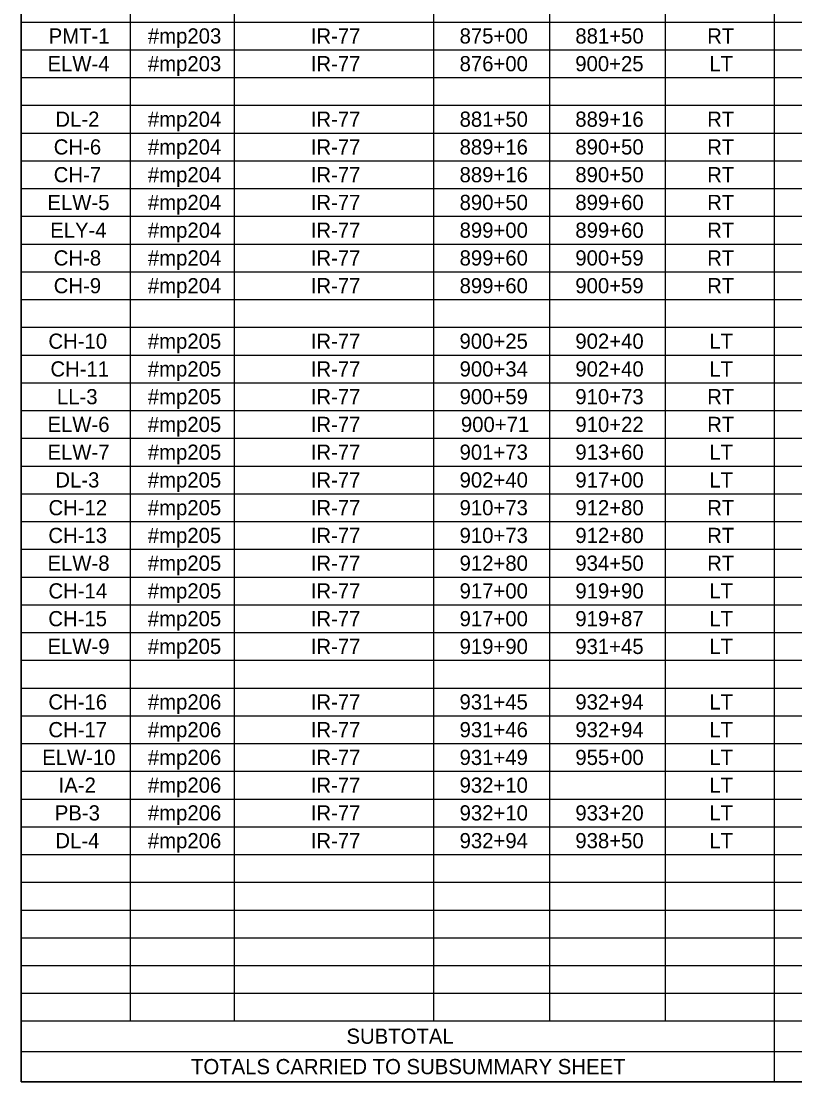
# Model space of a CAD drawing. Extents: x 91011267 to 91022583, y 37007614 to 37014266.
# Drawn here: x 91011277 to 91011661, y 37008895 to 37009420 of the extents above; entities that cross this region are included whole.
import ezdxf

# ---------------------------------------------------------------- set-up
doc = ezdxf.new("R2010")
doc.units = 0
doc.layers.add('SC_Scratch2', color=7, linetype='Continuous')
doc.layers.add('SH_Data', color=7, linetype='Continuous')

msp = doc.modelspace()

# ---------------------------------------------------------------- linework, layer by layer
at = {"layer": 'SC_Scratch2'}
msp.add_lwpolyline([(91011277.35, 37009944.63), (91012802.35, 37009944.63), (91012802.35, 37008894.63), (91011277.35, 37008894.63)], close=True, dxfattribs=at)
at = {"layer": 'SH_Data'}
for p, q in [((91011277.35, 37009570.43), (91011277.35, 37009364.35)), ((91011331.39, 37009570.43), (91011331.39, 37009364.35)), ((91011382.8, 37009570.43), (91011382.8, 37009364.35)), ((91011481.65, 37009570.43), (91011481.65, 37009364.35)), ((91011538.99, 37009570.43), (91011538.99, 37009364.35)), ((91011596.32, 37009570.43), (91011596.32, 37009364.35)), ((91011650.36, 37009570.43), (91011650.36, 37009364.35)), ((91011277.35, 37009419.31), (91011596.32, 37009419.31)), ((91011596.32, 37009419.31), (91011650.36, 37009419.31)), ((91011650.36, 37009419.31), (91011950.88, 37009419.31)), ((91011277.35, 37009405.57), (91011596.32, 37009405.57)), ((91011596.32, 37009405.57), (91011650.36, 37009405.57)), ((91011650.36, 37009405.57), (91011950.88, 37009405.57)), ((91011277.35, 37009391.83), (91011596.32, 37009391.83)), ((91011596.32, 37009391.83), (91011650.36, 37009391.83)), ((91011650.36, 37009391.83), (91011950.88, 37009391.83)), ((91011277.35, 37009378.09), (91011596.32, 37009378.09)), ((91011596.32, 37009378.09), (91011650.36, 37009378.09)), ((91011650.36, 37009378.09), (91011950.88, 37009378.09)), ((91011277.35, 37009364.35), (91011596.32, 37009364.35)), ((91011277.35, 37009364.35), (91011277.35, 37009350.61)), ((91011331.39, 37009364.35), (91011331.39, 37009350.61)), ((91011382.8, 37009364.35), (91011382.8, 37009350.61)), ((91011481.65, 37009364.35), (91011481.65, 37009350.61)), ((91011538.99, 37009364.35), (91011538.99, 37009350.61)), ((91011596.32, 37009364.35), (91011650.36, 37009364.35)), ((91011596.32, 37009364.35), (91011596.32, 37009350.61)), ((91011650.36, 37009364.35), (91011950.88, 37009364.35)), ((91011650.36, 37009364.35), (91011650.36, 37009350.61)), ((91011277.35, 37009350.61), (91011596.32, 37009350.61)), ((91011277.35, 37009350.61), (91011277.35, 37009336.88)), ((91011331.39, 37009350.61), (91011331.39, 37009336.88)), ((91011382.8, 37009350.61), (91011382.8, 37009336.88)), ((91011481.65, 37009350.61), (91011481.65, 37009336.88)), ((91011538.99, 37009350.61), (91011538.99, 37009336.88)), ((91011596.32, 37009350.61), (91011650.36, 37009350.61)), ((91011596.32, 37009350.61), (91011596.32, 37009336.88)), ((91011650.36, 37009350.61), (91011950.88, 37009350.61)), ((91011650.36, 37009350.61), (91011650.36, 37009336.88)), ((91011277.35, 37009336.88), (91011596.32, 37009336.88)), ((91011277.35, 37009336.88), (91011277.35, 37009295.66)), ((91011331.39, 37009336.88), (91011331.39, 37009295.66)), ((91011382.8, 37009336.88), (91011382.8, 37009295.66)), ((91011481.65, 37009336.88), (91011481.65, 37009295.66)), ((91011538.99, 37009336.88), (91011538.99, 37009295.66)), ((91011596.32, 37009336.88), (91011650.36, 37009336.88)), ((91011596.32, 37009336.88), (91011596.32, 37009295.66)), ((91011650.36, 37009336.88), (91011950.88, 37009336.88)), ((91011650.36, 37009336.88), (91011650.36, 37009295.66)), ((91011277.35, 37009323.14), (91011596.32, 37009323.14)), ((91011596.32, 37009323.14), (91011650.36, 37009323.14)), ((91011650.36, 37009323.14), (91011950.88, 37009323.14)), ((91011277.35, 37009309.4), (91011596.32, 37009309.4)), ((91011596.32, 37009309.4), (91011650.36, 37009309.4)), ((91011650.36, 37009309.4), (91011950.88, 37009309.4)), ((91011277.35, 37009295.66), (91011596.32, 37009295.66)), ((91011277.35, 37009295.66), (91011277.35, 37009281.92)), ((91011331.39, 37009295.66), (91011331.39, 37009281.92)), ((91011382.8, 37009295.66), (91011382.8, 37009281.92)), ((91011481.65, 37009295.66), (91011481.65, 37009281.92)), ((91011538.99, 37009295.66), (91011538.99, 37009281.92)), ((91011596.32, 37009295.66), (91011650.36, 37009295.66)), ((91011596.32, 37009295.66), (91011596.32, 37009281.92)), ((91011650.36, 37009295.66), (91011950.88, 37009295.66)), ((91011650.36, 37009295.66), (91011650.36, 37009281.92)), ((91011277.35, 37009281.92), (91011596.32, 37009281.92)), ((91011277.35, 37009281.92), (91011277.35, 37009268.18)), ((91011331.39, 37009281.92), (91011331.39, 37009268.18)), ((91011382.8, 37009281.92), (91011382.8, 37009268.18)), ((91011481.65, 37009281.92), (91011481.65, 37009268.18)), ((91011538.99, 37009281.92), (91011538.99, 37009268.18)), ((91011596.32, 37009281.92), (91011650.36, 37009281.92)), ((91011596.32, 37009281.92), (91011596.32, 37009268.18)), ((91011650.36, 37009281.92), (91011950.88, 37009281.92)), ((91011650.36, 37009281.92), (91011650.36, 37009268.18)), ((91011277.35, 37009268.18), (91011596.32, 37009268.18)), ((91011277.35, 37009268.18), (91011277.35, 37009226.97)), ((91011331.39, 37009268.18), (91011331.39, 37009226.97)), ((91011382.8, 37009268.18), (91011382.8, 37009226.97)), ((91011481.65, 37009268.18), (91011481.65, 37009226.97)), ((91011538.99, 37009268.18), (91011538.99, 37009226.97)), ((91011596.32, 37009268.18), (91011650.36, 37009268.18)), ((91011596.32, 37009268.18), (91011596.32, 37009226.97)), ((91011650.36, 37009268.18), (91011950.88, 37009268.18)), ((91011650.36, 37009268.18), (91011650.36, 37009226.97)), ((91011277.35, 37009254.45), (91011596.32, 37009254.45)), ((91011596.32, 37009254.45), (91011650.36, 37009254.45)), ((91011650.36, 37009254.45), (91011950.88, 37009254.45)), ((91011277.35, 37009240.71), (91011596.32, 37009240.71)), ((91011596.32, 37009240.71), (91011650.36, 37009240.71)), ((91011650.36, 37009240.71), (91011950.88, 37009240.71)), ((91011277.35, 37009226.97), (91011596.32, 37009226.97)), ((91011277.35, 37009226.97), (91011277.35, 37009213.23)), ((91011331.39, 37009226.97), (91011331.39, 37009213.23)), ((91011382.8, 37009226.97), (91011382.8, 37009213.23)), ((91011481.65, 37009226.97), (91011481.65, 37009213.23)), ((91011538.99, 37009226.97), (91011538.99, 37009213.23)), ((91011596.32, 37009226.97), (91011650.36, 37009226.97)), ((91011596.32, 37009226.97), (91011596.32, 37009213.23)), ((91011650.36, 37009226.97), (91011950.88, 37009226.97)), ((91011650.36, 37009226.97), (91011650.36, 37009213.23)), ((91011277.35, 37009213.23), (91011596.32, 37009213.23)), ((91011277.35, 37009213.23), (91011277.35, 37009199.49)), ((91011331.39, 37009213.23), (91011331.39, 37009199.49)), ((91011382.8, 37009213.23), (91011382.8, 37009199.49)), ((91011481.65, 37009213.23), (91011481.65, 37009199.49)), ((91011538.99, 37009213.23), (91011538.99, 37009199.49)), ((91011596.32, 37009213.23), (91011650.36, 37009213.23)), ((91011596.32, 37009213.23), (91011596.32, 37009199.49)), ((91011650.36, 37009213.23), (91011950.88, 37009213.23)), ((91011650.36, 37009213.23), (91011650.36, 37009199.49)), ((91011277.35, 37009199.49), (91011596.32, 37009199.49)), ((91011277.35, 37009199.49), (91011277.35, 37008894.63)), ((91011331.39, 37009199.49), (91011331.39, 37008924.73)), ((91011382.8, 37009199.49), (91011382.8, 37008924.73)), ((91011481.65, 37009199.49), (91011481.65, 37008924.73)), ((91011538.99, 37009199.49), (91011538.99, 37008924.73)), ((91011596.32, 37009199.49), (91011650.36, 37009199.49)), ((91011596.32, 37009199.49), (91011596.32, 37008924.73)), ((91011650.36, 37009199.49), (91011950.88, 37009199.49)), ((91011650.36, 37009199.49), (91011650.36, 37008894.63)), ((91011277.35, 37009185.75), (91011596.32, 37009185.75)), ((91011596.32, 37009185.75), (91011650.36, 37009185.75)), ((91011650.36, 37009185.75), (91011950.88, 37009185.75)), ((91011277.35, 37009172.02), (91011596.32, 37009172.02)), ((91011596.32, 37009172.02), (91011650.36, 37009172.02)), ((91011650.36, 37009172.02), (91011950.88, 37009172.02)), ((91011277.35, 37009158.28), (91011596.32, 37009158.28)), ((91011596.32, 37009158.28), (91011650.36, 37009158.28)), ((91011650.36, 37009158.28), (91011950.88, 37009158.28)), ((91011277.35, 37009144.54), (91011596.32, 37009144.54)), ((91011596.32, 37009144.54), (91011650.36, 37009144.54)), ((91011650.36, 37009144.54), (91011950.88, 37009144.54)), ((91011277.35, 37009130.8), (91011596.32, 37009130.8)), ((91011596.32, 37009130.8), (91011650.36, 37009130.8)), ((91011650.36, 37009130.8), (91011950.88, 37009130.8)), ((91011277.35, 37009117.06), (91011596.32, 37009117.06)), ((91011596.32, 37009117.06), (91011650.36, 37009117.06)), ((91011650.36, 37009117.06), (91011950.88, 37009117.06)), ((91011277.35, 37009103.32), (91011596.32, 37009103.32)), ((91011596.32, 37009103.32), (91011650.36, 37009103.32)), ((91011650.36, 37009103.32), (91011950.88, 37009103.32)), ((91011277.35, 37009089.59), (91011596.32, 37009089.59)), ((91011596.32, 37009089.59), (91011650.36, 37009089.59)), ((91011650.36, 37009089.59), (91011950.88, 37009089.59)), ((91011277.35, 37009075.85), (91011596.32, 37009075.85)), ((91011596.32, 37009075.85), (91011650.36, 37009075.85)), ((91011650.36, 37009075.85), (91011950.88, 37009075.85)), ((91011277.35, 37009062.11), (91011596.32, 37009062.11)), ((91011596.32, 37009062.11), (91011650.36, 37009062.11)), ((91011650.36, 37009062.11), (91011950.88, 37009062.11)), ((91011277.35, 37009048.37), (91011596.32, 37009048.37)), ((91011596.32, 37009048.37), (91011650.36, 37009048.37)), ((91011650.36, 37009048.37), (91011950.88, 37009048.37)), ((91011277.35, 37009034.63), (91011596.32, 37009034.63)), ((91011596.32, 37009034.63), (91011650.36, 37009034.63)), ((91011650.36, 37009034.63), (91011950.88, 37009034.63)), ((91011277.35, 37009020.89), (91011596.32, 37009020.89)), ((91011596.32, 37009020.89), (91011650.36, 37009020.89)), ((91011650.36, 37009020.89), (91011950.88, 37009020.89)), ((91011277.35, 37009007.16), (91011596.32, 37009007.16)), ((91011596.32, 37009007.16), (91011650.36, 37009007.16)), ((91011650.36, 37009007.16), (91011950.88, 37009007.16)), ((91011277.35, 37008993.42), (91011596.32, 37008993.42)), ((91011596.32, 37008993.42), (91011650.36, 37008993.42)), ((91011650.36, 37008993.42), (91011950.88, 37008993.42)), ((91011277.35, 37008979.68), (91011596.32, 37008979.68)), ((91011596.32, 37008979.68), (91011650.36, 37008979.68)), ((91011650.36, 37008979.68), (91011950.88, 37008979.68)), ((91011277.35, 37008965.94), (91011596.32, 37008965.94)), ((91011596.32, 37008965.94), (91011650.36, 37008965.94)), ((91011650.36, 37008965.94), (91011950.88, 37008965.94)), ((91011277.35, 37008952.2), (91011596.32, 37008952.2)), ((91011596.32, 37008952.2), (91011650.36, 37008952.2)), ((91011650.36, 37008952.2), (91011950.88, 37008952.2)), ((91011277.35, 37008938.46), (91011596.32, 37008938.46)), ((91011596.32, 37008938.46), (91011650.36, 37008938.46)), ((91011650.36, 37008938.46), (91011950.88, 37008938.46)), ((91011277.35, 37008924.73), (91011596.32, 37008924.73)), ((91011596.32, 37008924.73), (91011650.36, 37008924.73)), ((91011650.36, 37008924.73), (91011950.88, 37008924.73)), ((91011277.35, 37008909.68), (91011596.32, 37008909.68)), ((91011596.32, 37008909.68), (91011650.36, 37008909.68)), ((91011650.36, 37008909.68), (91011950.88, 37008909.68)), ((91011277.35, 37008894.63), (91011596.32, 37008894.63)), ((91011596.32, 37008894.63), (91011650.36, 37008894.63)), ((91011650.36, 37008894.63), (91011950.88, 37008894.63))]:
    msp.add_line(p, q, dxfattribs=at)

# ---------------------------------------------------------------- texts
for s, height, p in [('PMT-1', 7.523, (91011290.95, 37009408.67)), ('#mp203', 7.523, (91011340.1, 37009408.67)), ('IR-77', 7.523, (91011420.79, 37009408.67)), ('875+00', 7.523, (91011494.52, 37009408.67)), ('881+50', 7.523, (91011551.86, 37009408.67)), ('RT', 7.523, (91011617.17, 37009408.67)), ('ELW-4', 7.523, (91011290.4, 37009394.94)), ('#mp203', 7.523, (91011340.1, 37009394.94)), ('IR-77', 7.523, (91011420.79, 37009394.94)), ('876+00', 7.523, (91011494.52, 37009394.94)), ('900+25', 7.523, (91011551.82, 37009394.94)), ('LT', 7.523, (91011618.23, 37009394.94)), ('DL-2', 7.523, (91011294.3, 37009367.46)), ('#mp204', 7.523, (91011340.11, 37009367.46)), ('IR-77', 7.523, (91011420.79, 37009367.46)), ('881+50', 7.523, (91011494.52, 37009367.46)), ('889+16', 7.523, (91011551.84, 37009367.46)), ('RT', 7.523, (91011617.17, 37009367.46)), ('CH-6', 7.523, (91011293.47, 37009353.72)), ('#mp204', 7.523, (91011340.11, 37009353.72)), ('IR-77', 7.523, (91011420.79, 37009353.72)), ('889+16', 7.523, (91011494.51, 37009353.72)), ('890+50', 7.523, (91011551.86, 37009353.72)), ('RT', 7.523, (91011617.17, 37009353.72)), ('CH-7', 7.523, (91011293.47, 37009339.98)), ('#mp204', 7.523, (91011340.11, 37009339.98)), ('IR-77', 7.523, (91011420.79, 37009339.98)), ('889+16', 7.523, (91011494.51, 37009339.98)), ('890+50', 7.523, (91011551.86, 37009339.98)), ('RT', 7.523, (91011617.17, 37009339.98)), ('ELW-5', 7.523, (91011290.35, 37009326.24)), ('#mp204', 7.523, (91011340.11, 37009326.24)), ('IR-77', 7.523, (91011420.79, 37009326.24)), ('890+50', 7.523, (91011494.52, 37009326.24)), ('899+60', 7.523, (91011551.86, 37009326.24)), ('RT', 7.523, (91011617.17, 37009326.24)), ('ELY-4', 7.523, (91011291.71, 37009312.51)), ('#mp204', 7.523, (91011340.11, 37009312.51)), ('IR-77', 7.523, (91011420.79, 37009312.51)), ('899+00', 7.523, (91011494.52, 37009312.51)), ('899+60', 7.523, (91011551.86, 37009312.51)), ('RT', 7.523, (91011617.17, 37009312.51)), ('CH-8', 7.523, (91011293.46, 37009298.77)), ('#mp204', 7.523, (91011340.11, 37009298.77)), ('IR-77', 7.523, (91011420.79, 37009298.77)), ('899+60', 7.523, (91011494.52, 37009298.77)), ('900+59', 7.523, (91011551.84, 37009298.77)), ('RT', 7.523, (91011617.17, 37009298.77)), ('CH-9', 7.523, (91011293.46, 37009285.03)), ('#mp204', 7.523, (91011340.11, 37009285.03)), ('IR-77', 7.523, (91011420.79, 37009285.03)), ('899+60', 7.523, (91011494.52, 37009285.03)), ('900+59', 7.523, (91011551.84, 37009285.03)), ('RT', 7.523, (91011617.17, 37009285.03)), ('CH-10', 7.523, (91011290.83, 37009257.55)), ('#mp205', 7.523, (91011340.07, 37009257.55)), ('IR-77', 7.523, (91011420.79, 37009257.55)), ('900+25', 7.523, (91011494.48, 37009257.55)), ('902+40', 7.523, (91011551.86, 37009257.55)), ('LT', 7.523, (91011618.23, 37009257.55)), ('CH-11', 7.523, (91011291.83, 37009243.81)), ('#mp205', 7.523, (91011340.07, 37009243.81)), ('IR-77', 7.523, (91011420.79, 37009243.81)), ('900+34', 7.523, (91011494.52, 37009243.81)), ('902+40', 7.523, (91011551.86, 37009243.81)), ('LT', 7.523, (91011618.23, 37009243.81)), ('LL-3', 7.523, (91011295.05, 37009230.08)), ('#mp205', 7.523, (91011340.07, 37009230.08)), ('IR-77', 7.523, (91011420.79, 37009230.08)), ('900+59', 7.523, (91011494.5, 37009230.08)), ('910+73', 7.523, (91011551.84, 37009230.08)), ('RT', 7.523, (91011617.17, 37009230.08)), ('ELW-6', 7.523, (91011290.38, 37009216.34)), ('#mp205', 7.523, (91011340.07, 37009216.34)), ('900+71', 7.523, (91011495.17, 37009216.34)), ('910+22', 7.523, (91011551.88, 37009216.34)), ('IR-77', 7.523, (91011420.79, 37009216.34)), ('RT', 7.523, (91011617.17, 37009216.34)), ('ELW-7', 7.523, (91011290.38, 37009202.6)), ('#mp205', 7.523, (91011340.07, 37009202.6)), ('IR-77', 7.523, (91011420.79, 37009202.6)), ('901+73', 7.523, (91011494.51, 37009202.6)), ('913+60', 7.523, (91011551.86, 37009202.6)), ('LT', 7.523, (91011618.23, 37009202.6)), ('DL-3', 7.523, (91011294.26, 37009188.86)), ('#mp205', 7.523, (91011340.07, 37009188.86)), ('IR-77', 7.523, (91011420.79, 37009188.86)), ('902+40', 7.523, (91011494.52, 37009188.86)), ('917+00', 7.523, (91011551.86, 37009188.86)), ('LT', 7.523, (91011618.23, 37009188.86)), ('CH-12', 7.523, (91011290.86, 37009175.12)), ('#mp205', 7.523, (91011340.07, 37009175.12)), ('IR-77', 7.523, (91011420.79, 37009175.12)), ('910+73', 7.523, (91011494.51, 37009175.12)), ('912+80', 7.523, (91011551.86, 37009175.12)), ('RT', 7.523, (91011617.17, 37009175.12)), ('CH-13', 7.523, (91011290.82, 37009161.38)), ('#mp205', 7.523, (91011340.07, 37009161.38)), ('IR-77', 7.523, (91011420.79, 37009161.38)), ('910+73', 7.523, (91011494.51, 37009161.38)), ('912+80', 7.523, (91011551.86, 37009161.38)), ('RT', 7.523, (91011617.17, 37009161.38)), ('ELW-8', 7.523, (91011290.38, 37009147.65)), ('#mp205', 7.523, (91011340.07, 37009147.65)), ('IR-77', 7.523, (91011420.79, 37009147.65)), ('912+80', 7.523, (91011494.52, 37009147.65)), ('934+50', 7.523, (91011551.86, 37009147.65)), ('RT', 7.523, (91011617.17, 37009147.65)), ('CH-14', 7.523, (91011290.84, 37009133.91)), ('#mp205', 7.523, (91011340.07, 37009133.91)), ('IR-77', 7.523, (91011420.79, 37009133.91)), ('917+00', 7.523, (91011494.52, 37009133.91)), ('919+90', 7.523, (91011551.86, 37009133.91)), ('LT', 7.523, (91011618.23, 37009133.91)), ('CH-15', 7.523, (91011290.79, 37009120.17)), ('#mp205', 7.523, (91011340.07, 37009120.17)), ('IR-77', 7.523, (91011420.79, 37009120.17)), ('917+00', 7.523, (91011494.52, 37009120.17)), ('919+87', 7.523, (91011551.84, 37009120.17)), ('LT', 7.523, (91011618.23, 37009120.17)), ('ELW-9', 7.523, (91011290.38, 37009106.43)), ('#mp205', 7.523, (91011340.07, 37009106.43)), ('IR-77', 7.523, (91011420.79, 37009106.43)), ('919+90', 7.523, (91011494.52, 37009106.43)), ('931+45', 7.523, (91011551.82, 37009106.43)), ('LT', 7.523, (91011618.23, 37009106.43)), ('CH-16', 7.523, (91011290.82, 37009078.95)), ('#mp206', 7.523, (91011340.1, 37009078.95)), ('IR-77', 7.523, (91011420.79, 37009078.95)), ('931+45', 7.523, (91011494.48, 37009078.95)), ('932+94', 7.523, (91011551.86, 37009078.95)), ('LT', 7.523, (91011618.23, 37009078.95)), ('CH-17', 7.523, (91011290.82, 37009065.22)), ('#mp206', 7.523, (91011340.1, 37009065.22)), ('IR-77', 7.523, (91011420.79, 37009065.22)), ('931+46', 7.523, (91011494.51, 37009065.22)), ('932+94', 7.523, (91011551.86, 37009065.22)), ('LT', 7.523, (91011618.23, 37009065.22)), ('ELW-10', 7.523, (91011287.74, 37009051.48)), ('#mp206', 7.523, (91011340.1, 37009051.48)), ('IR-77', 7.523, (91011420.79, 37009051.48)), ('931+49', 7.523, (91011494.5, 37009051.48)), ('955+00', 7.523, (91011551.86, 37009051.48)), ('LT', 7.523, (91011618.23, 37009051.48)), ('IA-2', 7.523, (91011295.89, 37009037.74)), ('#mp206', 7.523, (91011340.1, 37009037.74)), ('932+10', 7.523, (91011494.52, 37009037.74)), ('IR-77', 7.523, (91011420.79, 37009037.74)), ('LT', 7.523, (91011618.23, 37009037.74)), ('PB-3', 7.523, (91011293.99, 37009024)), ('#mp206', 7.523, (91011340.1, 37009024)), ('IR-77', 7.523, (91011420.79, 37009024)), ('932+10', 7.523, (91011494.52, 37009024)), ('933+20', 7.523, (91011551.86, 37009024)), ('LT', 7.523, (91011618.23, 37009024)), ('DL-4', 7.523, (91011294.28, 37009010.26)), ('#mp206', 7.523, (91011340.1, 37009010.26)), ('IR-77', 7.523, (91011420.79, 37009010.26)), ('932+94', 7.523, (91011494.52, 37009010.26)), ('938+50', 7.523, (91011551.86, 37009010.26)), ('LT', 7.523, (91011618.23, 37009010.26)), ('SUBTOTAL', 7.523, (91011438.49, 37008913.44)), ('TOTALS CARRIED TO SUBSUMMARY SHEET', 7.5234, (91011361.48, 37008898.39))]:
    msp.add_text(s, height=height, dxfattribs=at).set_placement(p)

doc.saveas('drawing.dxf')
